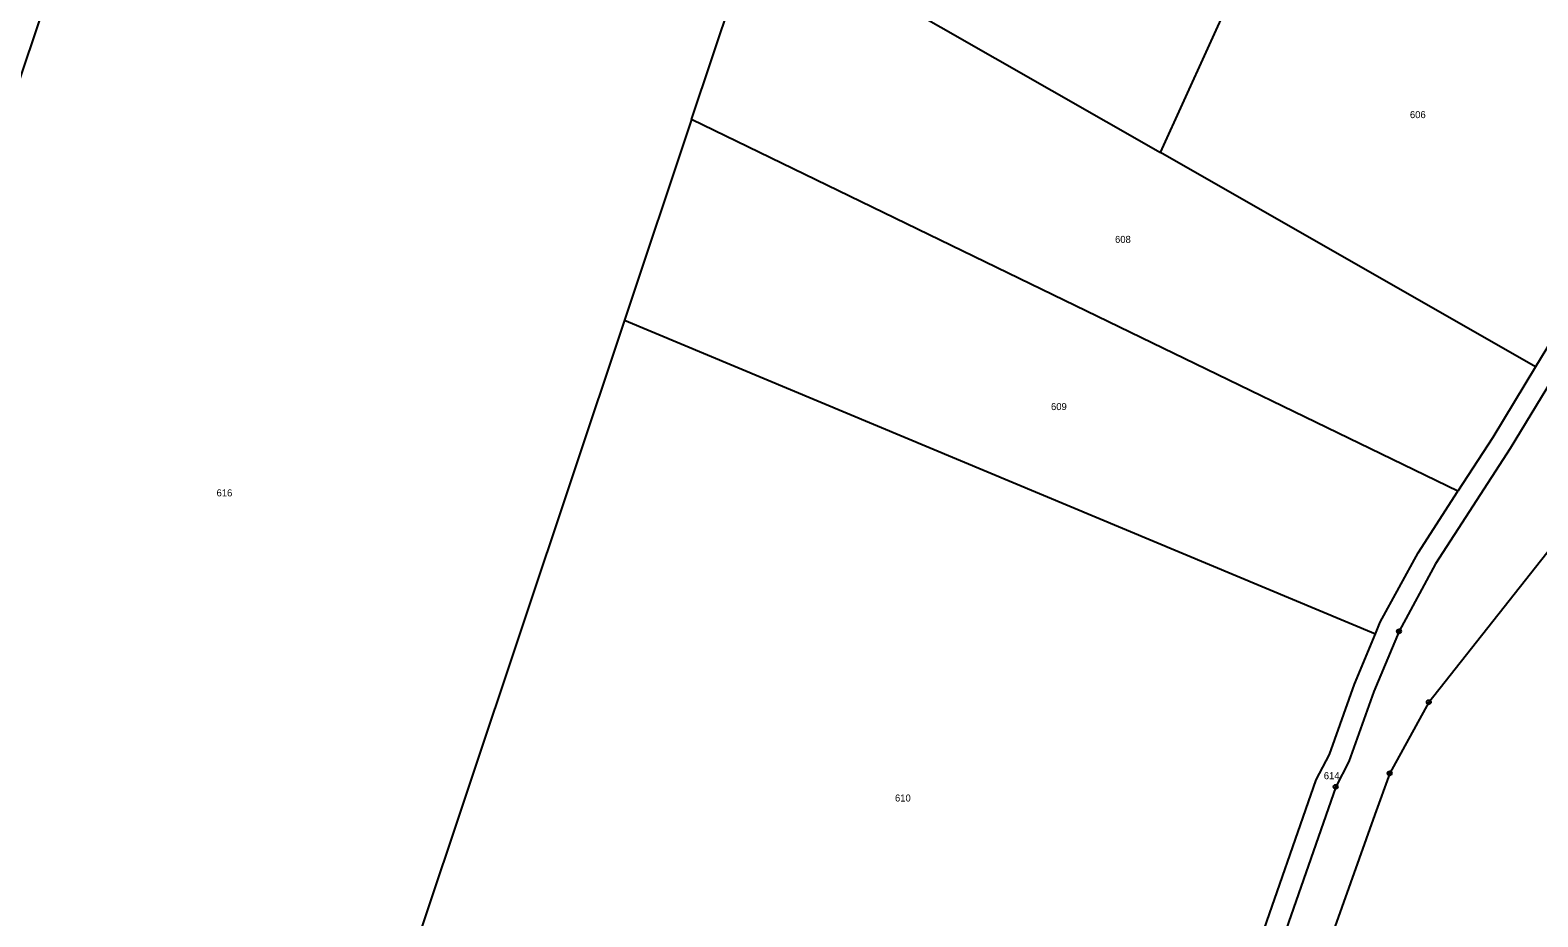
# Model space of a CAD drawing. Extents: x -759947 to -757003, y -1019641 to -1017100.
# Drawn here: x -758964.9 to -758601.9, y -1019166.6 to -1018953.1 of the extents above; entities that cross this region are included whole.
import ezdxf

# ---------------------------------------------------------------- set-up
doc = ezdxf.new("R2010")
doc.units = 0
doc.header["$LTSCALE"] = 0.68
doc.layers.add('1', color=7, linetype='Continuous', lineweight=25)
doc.layers.add('8', color=7, linetype='Continuous', lineweight=25)
doc.layers.add('2', color=7, linetype='Continuous')

msp = doc.modelspace()

# ---------------------------------------------------------------- linework, layer by layer
at = {"layer": '1'}
for p, q in [((-758963.97, -1018954.72), (-758908.93, -1018791.86)), ((-758692.75, -1018982.61), (-758661.26, -1018913.25)), ((-758805.63, -1018974.63), (-758789.78, -1018927.17)), ((-758789.78, -1018927.17), (-758692.75, -1018982.61)), ((-759019.01, -1019117.59), (-758963.97, -1018954.72)), ((-758805.63, -1018974.63), (-758821.77, -1019022.94)), ((-758713.18, -1019019.48), (-758805.63, -1018974.63)), ((-758602.45, -1019034.21), (-758692.75, -1018982.61)), ((-758587.95, -1019010.27), (-758602.45, -1019034.21)), ((-758583.47, -1019012.53), (-758608.51, -1019053.87)), ((-758621.09, -1019064.14), (-758713.18, -1019019.48)), ((-758821.77, -1019022.94), (-758871.69, -1019172.38)), ((-758821.77, -1019022.94), (-758640.96, -1019098.47)), ((-758602.45, -1019034.21), (-758612.73, -1019051.19)), ((-758612.73, -1019051.19), (-758621.09, -1019064.14)), ((-758608.51, -1019053.87), (-758626.47, -1019081.63)), ((-758630.7, -1019079.02), (-758621.09, -1019064.14)), ((-758639.8, -1019095.71), (-758630.7, -1019079.02)), ((-758628.12, -1019114.94), (-758598.52, -1019077.46)), ((-758626.47, -1019081.63), (-758635.29, -1019097.87)), ((-758646.05, -1019110.6), (-758640.96, -1019098.47)), ((-758635.29, -1019097.87), (-758641.39, -1019112.41)), ((-758640.96, -1019098.47), (-758639.8, -1019095.71)), ((-758652.06, -1019127.52), (-758646.05, -1019110.6)), ((-758641.39, -1019112.41), (-758647.35, -1019129.19)), ((-758628.12, -1019114.94), (-758637.53, -1019132.07)), ((-758655.24, -1019133.65), (-758652.06, -1019127.52)), ((-758647.35, -1019129.19), (-758650.53, -1019135.32)), ((-758682.25, -1019211.09), (-758655.24, -1019133.65)), ((-758637.53, -1019132.07), (-758641.09, -1019142)), ((-758650.53, -1019135.32), (-758677.53, -1019212.73)), ((-758641.09, -1019142), (-758660.59, -1019196.37))]:
    msp.add_line(p, q, dxfattribs=at)
at = {"layer": '8'}
for centre, radius in [((-758635.29, -1019097.8699), 0.5), ((-758635.29, -1019097.8699), 0.0303), ((-758628.12, -1019114.9399), 0.5), ((-758628.12, -1019114.9399), 0.0303), ((-758650.53, -1019135.3199), 0.5), ((-758637.53, -1019132.0699), 0.5), ((-758637.53, -1019132.0699), 0.0303), ((-758650.53, -1019135.3199), 0.0303)]:
    msp.add_circle(centre, radius, dxfattribs=at)

# ---------------------------------------------------------------- texts
at = {"layer": '2'}
for s, p in [('606', (-758632.66, -1018974.325)), ('608', (-758703.67, -1019004.365)), ('609', (-758719.09, -1019044.615)), ('616', (-758920.03, -1019065.395)), ('614', (-758653.4, -1019133.495)), ('610', (-758756.66, -1019138.865))]:
    msp.add_text(s, height=1.7, dxfattribs=at).set_placement(p)

doc.saveas('drawing.dxf')
